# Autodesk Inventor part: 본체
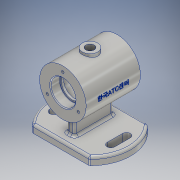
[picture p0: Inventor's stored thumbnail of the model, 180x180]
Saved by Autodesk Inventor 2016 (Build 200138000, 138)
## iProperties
Created: 2021-09
Part Number: 본체
Material: 알루미늄 6061
Document SubType Name: Modeling
Designer: pc-04
Density: 2.7 g/cm^3
Appearance: 알루미늄 - 평지
Mass: 467.678 g
Surface Area: 487.245 cm^2
Volume: 173.214 cm^3
Author: pc-04
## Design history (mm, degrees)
sketch "스케치1"
  geometry: L1 (0, 35)-(0, -35); L2 (0, 35)-(30, 35); L3 (30, 35)-(30, -35); L4 (30, -35)-(0, -35); 2 further points
  constraints: 8 end point, 2 coincident, 2 perpendicular, 1 horizontal, 1 midpoint, 1 vertical
  dimensions: "d0" = 70 distance of L1.start L1.end; "d1" = 60 diameter of L3 L1
revolve "회전1" sketch "스케치1" stored, may be unused: angle "d2" = 90 deg
sketch "스케치2"
  geometry: L1 (-30, 35)-(30, 35) reference; L2 (0, 35)-(0, -35); L3 (-30, -35)-(30, -35) reference; L4 (0, 35)-(16, 35); L5 (16, 35)-(16, 23); L6 (16, 23)-(14, 23); L7 (14, 23)-(14, 20); L8 (14, 20)-(25, 20); L9 (25, 20)-(25, -20); L10 (25, -20)-(14, -20); L11 (14, -20)-(14, -23); L12 (14, -23)-(16, -23); L13 (16, -23)-(16, -35); L14 (0, -35)-(16, -35); 1 further point
  constraints: 24 end point, 6 perpendicular, 6 point on line, 3 collinear, 2 midpoint, 1 vertical
  dimensions: "d3" = 32 diameter of L5 L2; "d4" = 28 diameter of L7 L2; "d5" = 50 diameter of L9 L2; "d6" = 12 distance of L4.end L5.end; "d7" = 40 distance of L8.end L9.end
revolve "회전2" sketch "스케치2" stored, may be unused: angle "d8" = 90 deg
fillet "모깎기1" dims "d9" = 0.3
fillet "모깎기2" dims "d10" = 3
chamfer "모따기1" distance "d11" = 1; stored, may be unused: second distance "d12" = 2, angle "d13" = 45 deg
chamfer "모따기2" distance "d14" = 1; stored, may be unused: second distance "d15" = 2, angle "d16" = 45 deg
sketch "스케치3" dims "d17" = 46
  geometry: 3 further points
  constraints: 2 vertical alignment, 1 coincident, 2 other
hole "구멍1" sketch "스케치3" at (0, 23) diameter "d18" = 3.242; stored, may be unused: countersink angle "d22" = 90 deg, drill point angle "d24" = 118 deg; dims "d19" = 8, "d20" = 4, "d21" = 2, "d23" = 10
node "작업 평면1"
sketch "스케치4"
  geometry: C1 r 10 at (0, 0); 1 further point
  constraints: 1 centre point, 1 coincident
  dimensions: "d29" = 20 diameter of C1
extrude "돌출1" join sketch "스케치4" stored distance "d30" = 10; taper "d31" = 0 deg
sketch "스케치5"
  geometry: 3 further points
  constraints: 2 coincident
node "작업 평면2"
sketch "스케치6"
  geometry: L1 (-37, 37.5)-(37, 37.5); L2 (37, -37.5)-(-37, -37.5); L3 (-37, 37.5)-(37, -37.5); L4 (37, 37.5)-(-37, -37.5); L5 (37, 37.5)-(37, 37.246); L6 (37, -37.246)-(37, -37.5); L7 (-37, -37.5)-(-37, -37.246); L8 (-37, 37.246)-(-37, 37.5); A1 r 52.5 centre (0, 0) between (-36.742, 37.5) and (-36.742, -37.5); A2 r 52.5 centre (0, 0) between (36.742, -37.5) and (36.742, 37.5); 2 further points
  constraints: 16 end point, 8 point on circle, 5 parallel, 4 point on line, 2 centre point, 2 midpoint, 2 perpendicular, 1 coincident, 1 horizontal, 1 vertical alignment
  dimensions: "d35" = 74 distance of L1.start L1.end; "d36" = 75 distance of L1.end L2.start; "d37" = 75 distance between parallel lines of L2 L1; "d38" = 52.5 radius of A1; "d39" = 52.5 radius of A2; "d40" = 74 distance of L2.start L2.end
extrude "돌출2" join sketch "스케치6" distance "d41" = 10; taper "d42" = 0 deg
sketch "스케치7"
  geometry: L1 (-5, -25)-(5, -25); L2 (5, -25)-(5, 25); L3 (5, 25)-(-5, 25); L4 (-5, 25)-(-5, -25); 3 further points
  constraints: 8 end point, 2 midpoint, 2 parallel, 1 horizontal, 1 horizontal alignment, 1 perpendicular, 1 vertical alignment
  dimensions: "d43" = 50 distance of L3.end L1.start; "d44" = 10 distance of L1.start L1.end
extrude "돌출3" join sketch "스케치7" stored distance "d45" = 10; taper "d46" = 0 deg
fillet "모깎기3" dims "d47" = 3
sketch "스케치8"
  geometry: L1 (37, 10)-(37, -10); L2 (42, 10)-(42, -10); L3 (32, -10)-(32, 10); A1 r 5 centre (37, 10) between (42, 10) and (32, 10); A2 r 5 centre (37, -10) between (32, -10) and (42, -10); A3 r 52.5 centre (0, 0) between (36.742, -37.5) and (36.742, 37.5) reference; 2 further points
  constraints: 8 end point, 4 point on circle, 4 tangent, 2 centre point, 1 horizontal alignment, 1 midpoint, 1 parallel, 1 vertical
  dimensions: "d48" = 37 distance of A3.centre point (37, 0); "d49" = 20 distance of L1.end L1.start; "d50" = 5 radius of A2
extrude "돌출4" cut sketch "스케치8" distance "d51" = 10; taper "d52" = 0 deg
fillet "모깎기4" dims "d53" = 3
node "작업 평면4"
sketch "스케치10"
  geometry: L1 (30, 35)-(30, -35) reference; L2 (-30, 35)-(30, 35) reference; 2 further points
  constraints: 1 other
  dimensions: "d58" = 30 distance from line of L1 point (0, 0); "d59" = 35 distance from line of L2 point (0, 0)
feature "엠보싱1" sketch "스케치10" dims "d3" = 32, "d4" = 28, "d5" = 50, "d6" = 12, "d7" = 40, "d60" = 0.5, "d61" = 0
hole "구멍2" sketch "스케치5" diameter "d62" = 10.917; stored, may be unused: countersink angle "d66" = 90 deg, drill point angle "d68" = 118 deg; dims "d63" = 24, "d64" = 4, "d65" = 2, "d67" = 29.1
node "솔리드1"
pattern_circular "원형 패턴1" dims angle "d26" = 360 deg
mirror "대칭1"
mirror "대칭2"
other parameters: "d28" = 33, "d32" = -62, "d33" = 105, "d57" = 36
